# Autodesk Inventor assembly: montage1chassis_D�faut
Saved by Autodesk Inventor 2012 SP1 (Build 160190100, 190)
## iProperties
Created: 2011-01
Part Number: montage1chassis_D�faut
Document SubType Name: Assembly
Designer: eric
Mass: 436.366 g
Surface Area: 3477.71 cm^2
Volume: 436.366 cm^3
Density: 1 g/cm^3
Author: eric
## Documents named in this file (26)
- D:\Cours\Inventor salle SI\chariot_de_golf_2008\chariot_de_golf_trolem\montage1chassis_Defaut.iam
- D:\Cours\Inventor salle SI\chariot_de_golf_2008\chariot_de_golf_trolem\bead16_Defaut.ipt
- D:\Cours\Inventor salle SI\chariot_de_golf_2008\chariot_de_golf_trolem\1boitier_assemble_Defaut.iam
- D:\Cours\Inventor salle SI\chariot_de_golf_2008\chariot_de_golf_trolem\1tube_Defaut.ipt
- D:\Cours\Inventor salle SI\chariot_de_golf_2008\chariot_de_golf_trolem\bead7_Defaut.ipt
- D:\Cours\Inventor salle SI\chariot_de_golf_2008\chariot_de_golf_trolem\bead3_Defaut.ipt
- D:\Cours\Inventor salle SI\chariot_de_golf_2008\chariot_de_golf_trolem\bead15_Defaut.ipt
- D:\Cours\Inventor salle SI\chariot_de_golf_2008\chariot_de_golf_trolem\bead4_Defaut.ipt
- D:\Cours\Inventor salle SI\chariot_de_golf_2008\chariot_de_golf_trolem\bead18_Defaut.ipt
- D:\Cours\Inventor salle SI\chariot_de_golf_2008\chariot_de_golf_trolem\1support_batterie_Defaut.iam
- D:\Cours\Inventor salle SI\chariot_de_golf_2008\chariot_de_golf_trolem\1bossage_Defaut.ipt
- D:\Cours\Inventor salle SI\chariot_de_golf_2008\chariot_de_golf_trolem\1tube_gauche_Defaut.ipt
- D:\Cours\Inventor salle SI\chariot_de_golf_2008\chariot_de_golf_trolem\46Vis CBLZ M5-10.ipt
- D:\Cours\Inventor salle SI\chariot_de_golf_2008\chariot_de_golf_trolem\bead8_Defaut.ipt
- D:\Cours\Inventor salle SI\chariot_de_golf_2008\chariot_de_golf_trolem\5.1roulement_12x28x8_Defaut.iam
- D:\Cours\Inventor salle SI\chariot_de_golf_2008\chariot_de_golf_trolem\41support_bas_Defaut.ipt
- D:\Cours\Inventor salle SI\chariot_de_golf_2008\chariot_de_golf_trolem\1bossage2_Defaut.ipt
- D:\Cours\Inventor salle SI\chariot_de_golf_2008\chariot_de_golf_trolem\bead14_Defaut.ipt
- D:\Cours\Inventor salle SI\chariot_de_golf_2008\chariot_de_golf_trolem\1chape_Defaut.ipt
- D:\Cours\Inventor salle SI\chariot_de_golf_2008\chariot_de_golf_trolem\bead5_Defaut.ipt
- D:\Cours\Inventor salle SI\chariot_de_golf_2008\chariot_de_golf_trolem\bead17_Defaut.ipt
- D:\Cours\Inventor salle SI\chariot_de_golf_2008\chariot_de_golf_trolem\1axe_8mm_Defaut.ipt
- D:\Cours\Inventor salle SI\chariot_de_golf_2008\chariot_de_golf_trolem\bead11_Defaut.ipt
- D:\Cours\Inventor salle SI\chariot_de_golf_2008\chariot_de_golf_trolem\bead6_Defaut.ipt
- D:\Cours\Inventor salle SI\chariot_de_golf_2008\chariot_de_golf_trolem\bead10_Defaut.ipt
- D:\Cours\Inventor salle SI\chariot_de_golf_2008\chariot_de_golf_trolem\1fixation_moteur_Defaut.ipt
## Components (28 placed, 25 different names)
1. bead16_Defaut:1
2. 1boitier_assemble_Defaut:1 [sub-assembly]
3. 1tube_Defaut:1
4. bead7_Defaut:1
5. bead3_Defaut:1
6. bead15_Defaut:1
7. bead4_Defaut:1
8. bead18_Defaut:1
9. 1support_batterie_Defaut:1 [sub-assembly]
10. 1bossage_Defaut:1
11. 1tube_gauche_Defaut:1
12. 46Vis CBLZ M5-10:1
13. bead15_Defaut:2
14. bead8_Defaut:1
15. 5.1roulement_12x28x8_Defaut:1 [sub-assembly]
16. 41support_bas_Defaut:1
17. 1bossage2_Defaut:1
18. bead14_Defaut:1
19. 1chape_Defaut:1
20. bead5_Defaut:1
21. bead14_Defaut:2
22. bead17_Defaut:1
23. 1axe_8mm_Defaut:1
24. bead11_Defaut:1
25. bead6_Defaut:1
26. bead10_Defaut:1
27. 1fixation_moteur_Defaut:1
28. 1bossage_Defaut:2
